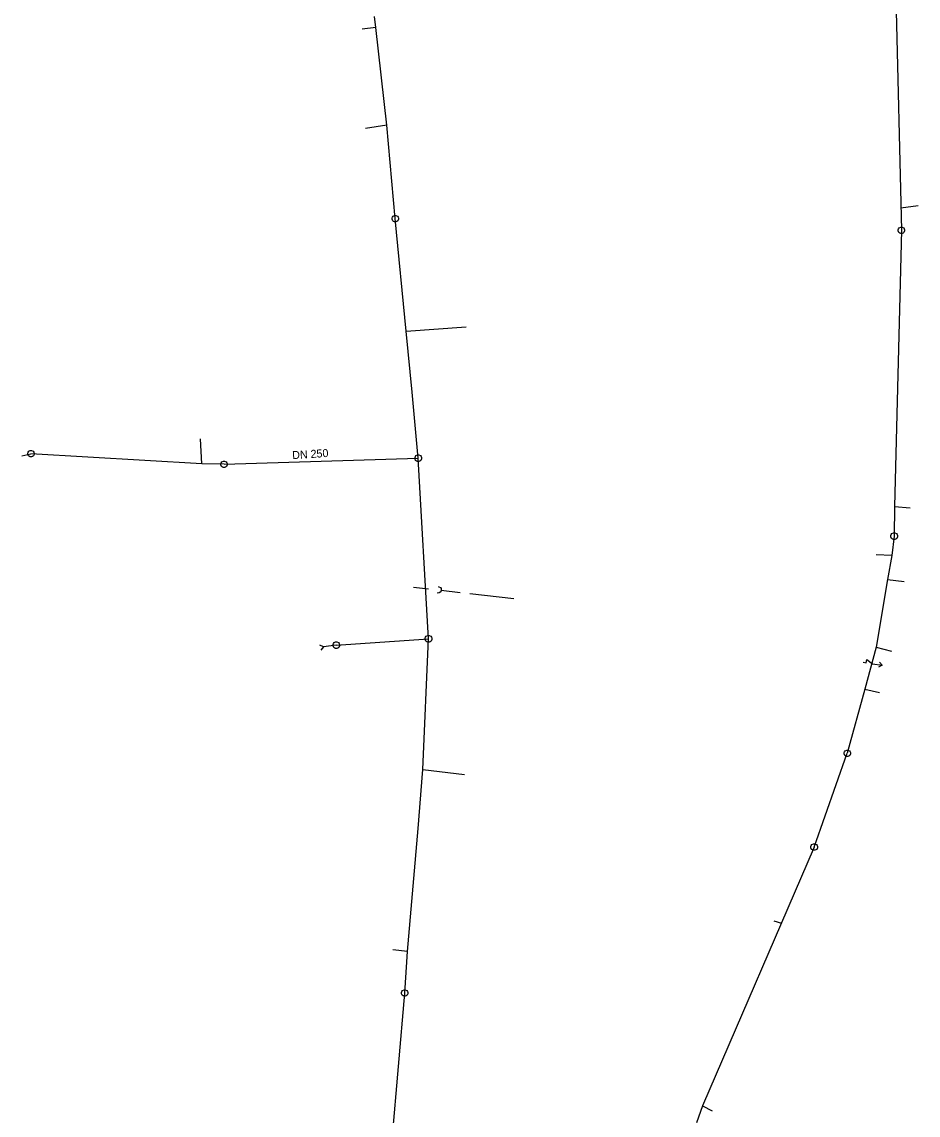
# Model space of a CAD drawing. Extents: x -717256 to -716843, y -1145423 to -1142840.
# Drawn here: x -717029.8 to -716889.8, y -1144905.8 to -1144735 of the extents above; entities that cross this region are included whole.
import ezdxf

# ---------------------------------------------------------------- set-up
doc = ezdxf.new("R2010")
doc.units = 0
for name, color, linetype in [('Vrstva 30', 7, 'Continuous'), ('Vrstva 31', 7, 'Continuous'), ('Vrstva 9', 7, 'Continuous')]:
    doc.layers.add(name, color=color, linetype=linetype)

msp = doc.modelspace()

# ---------------------------------------------------------------- linework, layer by layer
at = {"layer": 'Vrstva 30'}
for p, q in [((-716893.27, -1144729.746), (-716892.366, -1144767.564)), ((-716974.505, -1144735.855), (-716974.721, -1144734.14)), ((-716972.798, -1144751.145), (-716974.505, -1144735.855)), ((-716971.468, -1144765.737), (-716972.798, -1144751.145)), ((-716971.968, -1144765.637), (-716971.918, -1144765.487)), ((-716971.968, -1144765.837), (-716971.968, -1144765.637)), ((-716971.868, -1144766.087), (-716971.968, -1144765.837)), ((-716971.918, -1144765.487), (-716971.818, -1144765.337)), ((-716971.818, -1144765.337), (-716971.568, -1144765.237)), ((-716971.568, -1144765.237), (-716971.368, -1144765.237)), ((-716969.766, -1144783.334), (-716971.468, -1144765.737)), ((-716971.368, -1144765.237), (-716971.118, -1144765.337)), ((-716971.118, -1144765.337), (-716971.018, -1144765.487)), ((-716970.968, -1144765.837), (-716971.068, -1144766.087)), ((-716971.018, -1144765.487), (-716970.968, -1144765.637)), ((-716970.968, -1144765.637), (-716970.968, -1144765.837)), ((-716971.718, -1144766.187), (-716971.868, -1144766.087)), ((-716971.568, -1144766.237), (-716971.718, -1144766.187)), ((-716971.368, -1144766.237), (-716971.568, -1144766.237)), ((-716971.218, -1144766.187), (-716971.368, -1144766.237)), ((-716971.068, -1144766.087), (-716971.218, -1144766.187)), ((-716892.366, -1144767.564), (-716893.461, -1144810.697)), ((-716892.866, -1144767.464), (-716892.816, -1144767.314)), ((-716892.866, -1144767.664), (-716892.866, -1144767.464)), ((-716892.766, -1144767.914), (-716892.866, -1144767.664)), ((-716892.816, -1144767.314), (-716892.716, -1144767.164)), ((-716892.716, -1144767.164), (-716892.466, -1144767.064)), ((-716892.466, -1144767.064), (-716892.266, -1144767.064)), ((-716892.266, -1144767.064), (-716892.016, -1144767.164)), ((-716892.016, -1144767.164), (-716891.916, -1144767.314)), ((-716891.866, -1144767.664), (-716891.966, -1144767.914)), ((-716891.916, -1144767.314), (-716891.866, -1144767.464)), ((-716891.866, -1144767.464), (-716891.866, -1144767.664)), ((-716892.616, -1144768.014), (-716892.766, -1144767.914)), ((-716892.466, -1144768.064), (-716892.616, -1144768.014)), ((-716892.266, -1144768.064), (-716892.466, -1144768.064)), ((-716892.116, -1144768.014), (-716892.266, -1144768.064)), ((-716891.966, -1144767.914), (-716892.116, -1144768.014)), ((-716968.83, -1144792.848), (-716969.766, -1144783.334)), ((-716967.879, -1144803.157), (-716968.83, -1144792.848)), ((-717028.897, -1144802.363), (-717028.847, -1144802.213)), ((-717028.897, -1144802.563), (-717028.897, -1144802.363)), ((-717028.797, -1144802.813), (-717028.897, -1144802.563)), ((-717028.847, -1144802.213), (-717028.747, -1144802.063)), ((-717028.647, -1144802.913), (-717028.797, -1144802.813)), ((-717028.747, -1144802.063), (-717028.497, -1144801.963)), ((-717028.497, -1144802.963), (-717028.647, -1144802.913)), ((-717028.497, -1144801.963), (-717028.297, -1144801.963)), ((-717028.297, -1144802.963), (-717028.497, -1144802.963)), ((-717001.713, -1144804.045), (-717028.397, -1144802.463)), ((-717028.297, -1144801.963), (-717028.047, -1144802.063)), ((-717028.147, -1144802.913), (-717028.297, -1144802.963)), ((-717027.997, -1144802.813), (-717028.147, -1144802.913)), ((-717028.047, -1144802.063), (-717027.947, -1144802.213)), ((-717027.897, -1144802.563), (-717027.997, -1144802.813)), ((-717027.947, -1144802.213), (-717027.897, -1144802.363)), ((-717027.897, -1144802.363), (-717027.897, -1144802.563)), ((-716998.228, -1144804.114), (-716967.879, -1144803.157)), ((-716968.379, -1144803.057), (-716968.329, -1144802.907)), ((-716968.379, -1144803.257), (-716968.379, -1144803.057)), ((-716968.279, -1144803.507), (-716968.379, -1144803.257)), ((-716968.329, -1144802.907), (-716968.229, -1144802.757)), ((-716968.129, -1144803.607), (-716968.279, -1144803.507)), ((-716968.229, -1144802.757), (-716967.979, -1144802.657)), ((-716967.979, -1144802.657), (-716967.779, -1144802.657)), ((-716966.271, -1144831.385), (-716967.879, -1144803.157)), ((-716967.779, -1144802.657), (-716967.529, -1144802.757)), ((-716967.479, -1144803.507), (-716967.629, -1144803.607)), ((-716967.529, -1144802.757), (-716967.429, -1144802.907)), ((-716967.379, -1144803.257), (-716967.479, -1144803.507)), ((-716967.429, -1144802.907), (-716967.379, -1144803.057)), ((-716967.379, -1144803.057), (-716967.379, -1144803.257)), ((-716998.228, -1144804.114), (-717001.713, -1144804.045)), ((-716998.728, -1144804.014), (-716998.678, -1144803.864)), ((-716998.728, -1144804.214), (-716998.728, -1144804.014)), ((-716998.628, -1144804.464), (-716998.728, -1144804.214)), ((-716998.678, -1144803.864), (-716998.578, -1144803.714)), ((-716998.478, -1144804.564), (-716998.628, -1144804.464)), ((-716998.578, -1144803.714), (-716998.328, -1144803.614)), ((-716998.328, -1144804.614), (-716998.478, -1144804.564)), ((-716998.328, -1144803.614), (-716998.128, -1144803.614)), ((-716998.128, -1144804.614), (-716998.328, -1144804.614)), ((-716998.128, -1144803.614), (-716997.878, -1144803.714)), ((-716997.978, -1144804.564), (-716998.128, -1144804.614)), ((-716997.828, -1144804.464), (-716997.978, -1144804.564)), ((-716997.878, -1144803.714), (-716997.778, -1144803.864)), ((-716997.728, -1144804.214), (-716997.828, -1144804.464)), ((-716997.778, -1144803.864), (-716997.728, -1144804.014)), ((-716997.728, -1144804.014), (-716997.728, -1144804.214)), ((-716967.979, -1144803.657), (-716968.129, -1144803.607)), ((-716967.779, -1144803.657), (-716967.979, -1144803.657)), ((-716967.629, -1144803.607), (-716967.779, -1144803.657)), ((-716893.461, -1144810.697), (-716893.507, -1144815.338)), ((-716894.007, -1144815.238), (-716893.957, -1144815.088)), ((-716894.007, -1144815.438), (-716894.007, -1144815.238)), ((-716893.907, -1144815.688), (-716894.007, -1144815.438)), ((-716893.957, -1144815.088), (-716893.857, -1144814.938)), ((-716893.507, -1144815.338), (-716893.887, -1144818.36)), ((-716893.857, -1144814.938), (-716893.607, -1144814.838)), ((-716893.607, -1144814.838), (-716893.407, -1144814.838)), ((-716893.407, -1144814.838), (-716893.157, -1144814.938)), ((-716893.157, -1144814.938), (-716893.057, -1144815.088)), ((-716893.007, -1144815.438), (-716893.107, -1144815.688)), ((-716893.057, -1144815.088), (-716893.007, -1144815.238)), ((-716893.007, -1144815.238), (-716893.007, -1144815.438)), ((-716893.757, -1144815.788), (-716893.907, -1144815.688)), ((-716893.607, -1144815.838), (-716893.757, -1144815.788)), ((-716893.407, -1144815.838), (-716893.607, -1144815.838)), ((-716893.257, -1144815.788), (-716893.407, -1144815.838)), ((-716893.107, -1144815.688), (-716893.257, -1144815.788)), ((-716893.887, -1144818.36), (-716894.52, -1144822.104)), ((-716894.52, -1144822.104), (-716896.313, -1144832.694)), ((-716981.18, -1144832.27), (-716981.13, -1144832.12)), ((-716981.18, -1144832.47), (-716981.18, -1144832.27)), ((-716981.08, -1144832.72), (-716981.18, -1144832.47)), ((-716981.13, -1144832.12), (-716981.03, -1144831.97)), ((-716981.03, -1144831.97), (-716980.78, -1144831.87)), ((-716980.78, -1144831.87), (-716980.58, -1144831.87)), ((-716980.68, -1144832.37), (-716966.271, -1144831.385)), ((-716980.58, -1144831.87), (-716980.33, -1144831.97)), ((-716980.33, -1144831.97), (-716980.23, -1144832.12)), ((-716980.18, -1144832.47), (-716980.28, -1144832.72)), ((-716980.23, -1144832.12), (-716980.18, -1144832.27)), ((-716980.18, -1144832.27), (-716980.18, -1144832.47)), ((-716967.172, -1144851.81), (-716966.271, -1144831.385)), ((-716966.771, -1144831.285), (-716966.721, -1144831.135)), ((-716966.771, -1144831.485), (-716966.771, -1144831.285)), ((-716966.671, -1144831.735), (-716966.771, -1144831.485)), ((-716966.721, -1144831.135), (-716966.621, -1144830.985)), ((-716966.521, -1144831.835), (-716966.671, -1144831.735)), ((-716966.621, -1144830.985), (-716966.371, -1144830.885)), ((-716966.371, -1144831.885), (-716966.521, -1144831.835)), ((-716966.371, -1144830.885), (-716966.171, -1144830.885)), ((-716966.171, -1144831.885), (-716966.371, -1144831.885)), ((-716966.171, -1144830.885), (-716965.921, -1144830.985)), ((-716966.021, -1144831.835), (-716966.171, -1144831.885)), ((-716965.871, -1144831.735), (-716966.021, -1144831.835)), ((-716965.921, -1144830.985), (-716965.821, -1144831.135)), ((-716965.771, -1144831.485), (-716965.871, -1144831.735)), ((-716965.821, -1144831.135), (-716965.771, -1144831.285)), ((-716965.771, -1144831.285), (-716965.771, -1144831.485)), ((-716980.93, -1144832.82), (-716981.08, -1144832.72)), ((-716980.78, -1144832.87), (-716980.93, -1144832.82)), ((-716980.58, -1144832.87), (-716980.78, -1144832.87)), ((-716980.43, -1144832.82), (-716980.58, -1144832.87)), ((-716980.28, -1144832.72), (-716980.43, -1144832.82)), ((-716896.313, -1144832.694), (-716898.089, -1144839.219)), ((-716898.089, -1144839.219), (-716900.822, -1144849.26)), ((-716906.001, -1144863.916), (-716900.822, -1144849.26)), ((-716901.322, -1144849.16), (-716901.272, -1144849.01)), ((-716901.322, -1144849.36), (-716901.322, -1144849.16)), ((-716901.222, -1144849.61), (-716901.322, -1144849.36)), ((-716901.272, -1144849.01), (-716901.172, -1144848.86)), ((-716901.072, -1144849.71), (-716901.222, -1144849.61)), ((-716901.172, -1144848.86), (-716900.922, -1144848.76)), ((-716900.922, -1144848.76), (-716900.722, -1144848.76)), ((-716900.722, -1144848.76), (-716900.472, -1144848.86)), ((-716900.422, -1144849.61), (-716900.572, -1144849.71)), ((-716900.472, -1144848.86), (-716900.372, -1144849.01)), ((-716900.322, -1144849.36), (-716900.422, -1144849.61)), ((-716900.372, -1144849.01), (-716900.322, -1144849.16)), ((-716900.322, -1144849.16), (-716900.322, -1144849.36)), ((-716900.922, -1144849.76), (-716901.072, -1144849.71)), ((-716900.722, -1144849.76), (-716900.922, -1144849.76)), ((-716900.572, -1144849.71), (-716900.722, -1144849.76)), ((-716967.881, -1144861), (-716967.172, -1144851.81)), ((-716969.573, -1144880.225), (-716967.881, -1144861)), ((-716906.001, -1144863.916), (-716923.436, -1144904.319)), ((-716906.501, -1144863.816), (-716906.451, -1144863.666)), ((-716906.501, -1144864.016), (-716906.501, -1144863.816)), ((-716906.401, -1144864.266), (-716906.501, -1144864.016)), ((-716906.451, -1144863.666), (-716906.351, -1144863.516)), ((-716906.251, -1144864.366), (-716906.401, -1144864.266)), ((-716906.351, -1144863.516), (-716906.101, -1144863.416)), ((-716906.101, -1144864.416), (-716906.251, -1144864.366)), ((-716906.101, -1144863.416), (-716905.901, -1144863.416)), ((-716905.901, -1144864.416), (-716906.101, -1144864.416)), ((-716905.901, -1144863.416), (-716905.651, -1144863.516)), ((-716905.751, -1144864.366), (-716905.901, -1144864.416)), ((-716905.601, -1144864.266), (-716905.751, -1144864.366)), ((-716905.651, -1144863.516), (-716905.551, -1144863.666)), ((-716905.501, -1144864.016), (-716905.601, -1144864.266)), ((-716905.551, -1144863.666), (-716905.501, -1144863.816)), ((-716905.501, -1144863.816), (-716905.501, -1144864.016)), ((-716969.992, -1144886.715), (-716969.573, -1144880.225)), ((-716972.263, -1144913.081), (-716969.992, -1144886.715)), ((-716970.492, -1144886.615), (-716970.442, -1144886.465)), ((-716970.492, -1144886.815), (-716970.492, -1144886.615)), ((-716970.392, -1144887.065), (-716970.492, -1144886.815)), ((-716970.442, -1144886.465), (-716970.342, -1144886.315)), ((-716970.242, -1144887.165), (-716970.392, -1144887.065)), ((-716970.342, -1144886.315), (-716970.092, -1144886.215)), ((-716970.092, -1144887.215), (-716970.242, -1144887.165)), ((-716970.092, -1144886.215), (-716969.892, -1144886.215)), ((-716969.892, -1144887.215), (-716970.092, -1144887.215)), ((-716969.892, -1144886.215), (-716969.642, -1144886.315)), ((-716969.742, -1144887.165), (-716969.892, -1144887.215)), ((-716969.592, -1144887.065), (-716969.742, -1144887.165)), ((-716969.642, -1144886.315), (-716969.542, -1144886.465)), ((-716969.492, -1144886.815), (-716969.592, -1144887.065)), ((-716969.542, -1144886.465), (-716969.492, -1144886.615)), ((-716969.492, -1144886.615), (-716969.492, -1144886.815)), ((-716923.436, -1144904.319), (-716924.397, -1144906.971))]:
    msp.add_line(p, q, dxfattribs=at)
at = {"layer": 'Vrstva 31'}
for p, q in [((-716974.505, -1144735.855), (-716976.62, -1144736.117)), ((-716972.798, -1144751.145), (-716976.099, -1144751.646)), ((-716892.456, -1144764.063), (-716889.756, -1144763.672)), ((-716969.766, -1144783.334), (-716960.385, -1144782.665)), ((-717001.713, -1144804.045), (-717001.889, -1144800.135)), ((-717029.817, -1144802.794), (-717028.397, -1144802.463)), ((-716893.461, -1144810.697), (-716891.012, -1144810.933)), ((-716893.887, -1144818.36), (-716896.294, -1144818.275)), ((-716894.52, -1144822.104), (-716891.949, -1144822.428)), ((-716982.68, -1144832.65), (-716983.27, -1144832.38)), ((-716980.68, -1144832.37), (-716982.68, -1144832.65)), ((-716982.68, -1144832.65), (-716983.09, -1144833.15)), ((-716896.313, -1144832.694), (-716893.93, -1144833.285)), ((-716898.089, -1144839.219), (-716895.797, -1144839.759)), ((-716967.172, -1144851.81), (-716960.645, -1144852.568)), ((-716912.324, -1144875.44), (-716911.086, -1144875.818)), ((-716969.573, -1144880.225), (-716971.864, -1144879.966)), ((-716923.436, -1144904.319), (-716921.935, -1144905.106))]:
    msp.add_line(p, q, dxfattribs=at)
at = {"layer": 'Vrstva 9'}
for p, q in [((-716968.601, -1144823.287), (-716966.283, -1144823.551)), ((-716964.736, -1144823.224), (-716964.637, -1144823.236)), ((-716964.637, -1144823.236), (-716964.4, -1144823.363)), ((-716964.307, -1144823.877), (-716964.435, -1144824.114)), ((-716964.4, -1144823.363), (-716964.317, -1144823.524)), ((-716964.317, -1144823.524), (-716964.285, -1144823.678)), ((-716964.285, -1144823.678), (-716964.307, -1144823.877)), ((-716964.296, -1144823.778), (-716961.315, -1144824.118)), ((-716964.75, -1144824.229), (-716964.849, -1144824.218)), ((-716964.595, -1144824.197), (-716964.75, -1144824.229)), ((-716964.435, -1144824.114), (-716964.595, -1144824.197)), ((-716959.825, -1144824.288), (-716952.917, -1144825.077)), ((-716898.351, -1144835.04), (-716897.857, -1144835.118)), ((-716897.857, -1144835.118), (-716897.779, -1144834.624)), ((-716897.779, -1144834.624), (-716896.87, -1144835.275)), ((-716896.87, -1144835.275), (-716895.388, -1144835.509)), ((-716895.388, -1144835.509), (-716895.944, -1144835.826)), ((-716895.819, -1144835.036), (-716895.388, -1144835.509))]:
    msp.add_line(p, q, dxfattribs=at)

# ---------------------------------------------------------------- texts
at = {"layer": 'Vrstva 30'}
msp.add_text('DN 250', height=1.25, rotation=3.6, dxfattribs=at).set_placement((-716987.534, -1144803.314))

doc.saveas('drawing.dxf')
